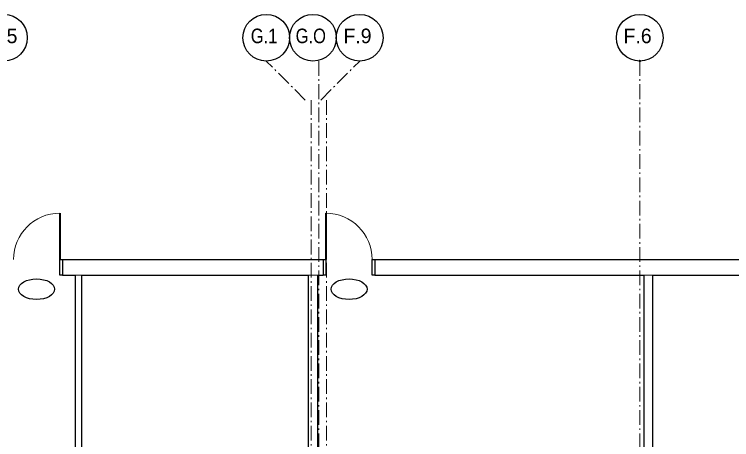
# Model space of a CAD drawing. Extents: x 10076 to 10305, y 10052 to 10157.
# Drawn here: x 10164.84 to 10211.27, y 10129.6 to 10157.12 of the extents above; entities that cross this region are included whole.
import ezdxf
from ezdxf.enums import TextEntityAlignment as Align

# ---------------------------------------------------------------- set-up
doc = ezdxf.new("R2010")
doc.units = 0
doc.header["$LTSCALE"] = 0.19
doc.header["$PDMODE"] = 32
doc.header["$PDSIZE"] = 0.095
doc.linetypes.add('DOT_DASHED', pattern=[7.7, 5, -1.2, 0.3, -1.2])
for name, color, linetype, lineweight in [('1', 7, 'Continuous', 13), ('10', 7, 'DOT_DASHED', 13), ('11', 7, 'Continuous', 25), ('23', 7, 'Continuous', 25), ('25', 7, 'Continuous', 13), ('26', 7, 'Continuous', 25), ('42', 7, 'Continuous', 25)]:
    doc.layers.add(name, color=color, linetype=linetype, lineweight=lineweight)

msp = doc.modelspace()

# ---------------------------------------------------------------- linework, layer by layer
at = {"layer": '1'}
for points in [[(10167.948, 10141.2504), (10167.948, 10140.2504), (10184.8356, 10140.2504), (10184.8356, 10141.2504)], [(10188.169, 10141.2504), (10188.169, 10140.2504), (10233.4943, 10140.2504), (10233.4943, 10141.2504)], [(10168.7836, 10140.2504), (10168.7836, 10125.9796), (10169.1898, 10125.9796), (10169.1898, 10140.2504)], [(10183.8669, 10125.9796), (10183.8669, 10140.2504), (10184.4711, 10140.2504), (10184.4711, 10125.9796)], [(10205.6117, 10140.2504), (10205.6117, 10126.7087), (10206.1742, 10126.7087), (10206.1742, 10140.2504)]]:
    msp.add_lwpolyline(points, close=True, dxfattribs=at)
at = {"layer": '10'}
for p, q in [((10183.669, 10151.5744), (10181.1469, 10154.0964)), ((10184.544, 10154.0964), (10184.544, 10104.0964)), ((10184.669, 10151.5744), (10187.191, 10154.0964)), ((10205.32, 10154.0964), (10205.32, 10118.7504)), ((10184.044, 10151.5744), (10184.044, 10104.0964)), ((10185.044, 10151.5744), (10185.044, 10104.0964))]:
    msp.add_line(p, q, dxfattribs=at)
msp.add_point((10205.32, 10154.0964), dxfattribs=at)
at = {"layer": '11'}
for centre in [(10164.169, 10155.6074), (10181.1469, 10155.6074), (10184.169, 10155.6074), (10187.191, 10155.6074), (10205.32, 10155.6074)]:
    msp.add_circle(centre, 1.511, dxfattribs=at)
at = {"layer": '23'}
for p, q in [((10167.948, 10141.2504), (10167.948, 10140.2504)), ((10167.948, 10141.2504), (10184.8356, 10141.2504)), ((10184.8356, 10141.2504), (10184.8356, 10140.2504)), ((10188.169, 10141.2504), (10233.4943, 10141.2504)), ((10188.169, 10141.2504), (10188.169, 10140.2504)), ((10167.948, 10140.2504), (10168.7836, 10140.2504)), ((10168.7836, 10140.2504), (10168.7836, 10125.3754)), ((10169.1898, 10140.2504), (10169.1898, 10125.9796)), ((10169.1898, 10140.2504), (10183.8669, 10140.2504)), ((10183.8669, 10140.2504), (10183.8669, 10125.9796)), ((10184.4711, 10140.2504), (10184.4711, 10125.9796)), ((10184.4711, 10140.2504), (10184.8356, 10140.2504)), ((10188.169, 10140.2504), (10205.6117, 10140.2504)), ((10205.6117, 10126.7087), (10205.6117, 10140.2504)), ((10206.1742, 10126.7087), (10206.1742, 10140.2504)), ((10206.1742, 10140.2504), (10233.4943, 10140.2504))]:
    msp.add_line(p, q, dxfattribs=at)
at = {"layer": '25', "lineweight": 40}
for p, q in [((10167.7814, 10144.2504), (10167.7814, 10141.2504)), ((10185.0023, 10144.2504), (10185.0023, 10141.2504))]:
    msp.add_line(p, q, dxfattribs=at)
at = {"layer": '25'}
for centre, start, end in [((10167.7814, 10141.2504), 89.99998, 179.99998), ((10185.0023, 10141.2504), 0.00001, 90)]:
    msp.add_arc(centre, 3, start, end, dxfattribs=at)
at = {"layer": '26'}
for points in [[(10167.948, 10140.2504), (10167.7814, 10140.2504), (10167.7814, 10141.2504), (10167.948, 10141.2504)], [(10184.8356, 10141.2504), (10185.0023, 10141.2504), (10185.0023, 10140.2504), (10184.8356, 10140.2504)], [(10188.169, 10140.2504), (10188.0023, 10140.2504), (10188.0023, 10141.2504), (10188.169, 10141.2504)]]:
    msp.add_lwpolyline(points, dxfattribs=at)
at = {"layer": '42'}
for centre in [(10166.2814, 10139.3337), (10186.5023, 10139.3337)]:
    msp.add_ellipse(centre, major_axis=(1.1667, 0), ratio=0.571429, dxfattribs=at)

# ---------------------------------------------------------------- texts
at = {"layer": '11'}
for s, p in [('G.5', (10164.0274, 10155.2531)), ('F.9', (10187.0494, 10155.2531)), ('F.6', (10205.1784, 10155.2531))]:
    msp.add_text(s, height=0.9412, dxfattribs=at).set_placement(p, align=Align.CENTER)
at = {"layer": '11', "width": 0.85}
for s, p in [('G.1', (10181.0053, 10155.2531)), ('G.O', (10184.0274, 10155.2531))]:
    msp.add_text(s, height=0.9412, dxfattribs=at).set_placement(p, align=Align.CENTER)

doc.saveas('drawing.dxf')
